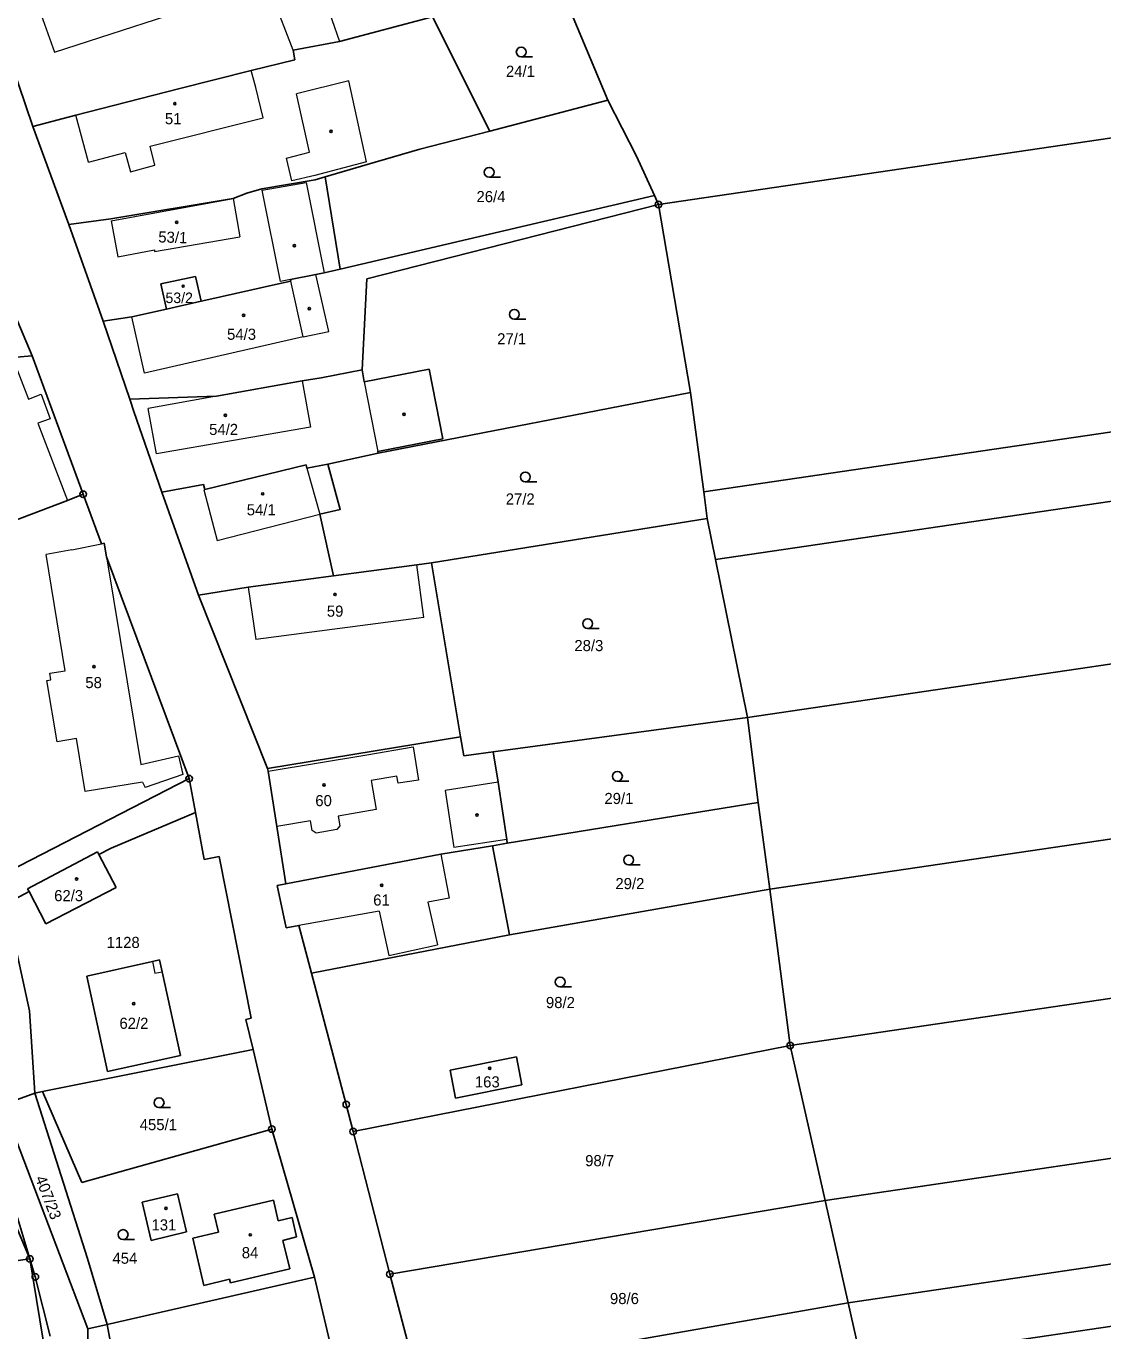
# Model space of a CAD drawing. Extents: x -618848 to -615803, y -1044450 to -1042254.
# Drawn here: x -616929.8 to -616765.3, y -1043345.1 to -1043145.8 of the extents above; entities that cross this region are included whole.
import ezdxf
from ezdxf.enums import TextEntityAlignment as Align

# ---------------------------------------------------------------- set-up
doc = ezdxf.new("R2010")
doc.units = 0
doc.header["$LTSCALE"] = 0.68
for name, color, linetype, lineweight in [('1', 7, 'Continuous', 25), ('3', 7, 'Continuous', 25), ('4', 7, 'Continuous', 13), ('5', 7, 'Continuous', 25), ('8', 7, 'Continuous', 25)]:
    doc.layers.add(name, color=color, linetype=linetype, lineweight=lineweight)
doc.layers.add('2', color=7, linetype='Continuous')

msp = doc.modelspace()

# ---------------------------------------------------------------- linework, layer by layer
at = {"layer": '1'}
for p, q in [((-616840.92, -1043157.18), (-616848.28, -1043139.55)), ((-616928.73, -1043161.2), (-616934.26, -1043144.93)), ((-616881.88, -1043148.18), (-616867.68, -1043144.42)), ((-616867.68, -1043144.42), (-616858.92, -1043161.88)), ((-616648.67, -1043145.97), (-616833.15, -1043173.1)), ((-616881.88, -1043148.18), (-616888.98, -1043149.52)), ((-616888.72, -1043151.02), (-616888.98, -1043149.52)), ((-616895.37, -1043152.64), (-616888.72, -1043151.02)), ((-616895.37, -1043152.64), (-616906.46, -1043155.41)), ((-616906.46, -1043155.41), (-616922.14, -1043159.46)), ((-616858.92, -1043161.88), (-616840.92, -1043157.18)), ((-616836.53, -1043165.69), (-616840.92, -1043157.18)), ((-616928.73, -1043161.2), (-616922.14, -1043159.46)), ((-616928.73, -1043161.2), (-616923.21, -1043176.13)), ((-616869.61, -1043164.66), (-616858.92, -1043161.88)), ((-616877.64, -1043167), (-616869.61, -1043164.66)), ((-616884.06, -1043168.87), (-616877.64, -1043167)), ((-616833.77, -1043171.73), (-616836.53, -1043165.69)), ((-616893.73, -1043170.72), (-616885.62, -1043169.32)), ((-616885.62, -1043169.32), (-616884.06, -1043168.87)), ((-616884.06, -1043168.87), (-616881.78, -1043182.98)), ((-616898.12, -1043172.18), (-616896.02, -1043171.37)), ((-616896.02, -1043171.37), (-616893.73, -1043170.72)), ((-616916.81, -1043175.29), (-616898.12, -1043172.18)), ((-616833.77, -1043171.73), (-616881.78, -1043182.98)), ((-616833.15, -1043173.1), (-616877.7, -1043184.44)), ((-616833.77, -1043171.73), (-616833.15, -1043173.1)), ((-616833.15, -1043173.1), (-616828.26, -1043201.79)), ((-616923.21, -1043176.13), (-616916.81, -1043175.29)), ((-616923.21, -1043176.13), (-616917.99, -1043190.91)), ((-616881.78, -1043182.98), (-616884.23, -1043183.55)), ((-616909.16, -1043185.21), (-616903.87, -1043184.1)), ((-616908.29, -1043189.06), (-616909.16, -1043185.21)), ((-616903.87, -1043184.1), (-616903, -1043187.86)), ((-616890.77, -1043185.12), (-616902.3, -1043187.72)), ((-616889.31, -1043184.79), (-616890.77, -1043185.12)), ((-616885.48, -1043183.8), (-616889.36, -1043184.57)), ((-616889.36, -1043184.57), (-616889.31, -1043184.79)), ((-616884.23, -1043183.55), (-616885.48, -1043183.8)), ((-616878.44, -1043198.36), (-616877.7, -1043184.44)), ((-616928.83, -1043196.23), (-616931.97, -1043188.74)), ((-616908.29, -1043189.06), (-616913.6, -1043190.27)), ((-616903, -1043187.86), (-616908.29, -1043189.06)), ((-616902.3, -1043187.72), (-616903, -1043187.86)), ((-616826.24, -1043216.98), (-616635.31, -1043188.92)), ((-616913.6, -1043190.27), (-616917.99, -1043190.91)), ((-616913.9, -1043202.82), (-616917.99, -1043190.91)), ((-616928.83, -1043196.23), (-616941.77, -1043197.23)), ((-616921.05, -1043217.36), (-616928.83, -1043196.23)), ((-616878.44, -1043198.36), (-616884.71, -1043199.56)), ((-616878.44, -1043198.36), (-616878.1, -1043200.2)), ((-616868.19, -1043198.27), (-616878.1, -1043200.2)), ((-616868.19, -1043198.27), (-616866.12, -1043208.87)), ((-616632.17, -1043199.04), (-616824.43, -1043227.31)), ((-616887.57, -1043200.01), (-616900.67, -1043202.37)), ((-616884.71, -1043199.56), (-616887.57, -1043200.01)), ((-616913.9, -1043202.82), (-616900.67, -1043202.37)), ((-616913.28, -1043204.69), (-616913.9, -1043202.82)), ((-616828.26, -1043201.79), (-616875.97, -1043211.1)), ((-616826.24, -1043216.98), (-616828.26, -1043201.79)), ((-616909.01, -1043217.03), (-616913.28, -1043204.69)), ((-616876.03, -1043210.8), (-616866.12, -1043208.87)), ((-616875.97, -1043211.1), (-616883.67, -1043212.75)), ((-616876.03, -1043210.8), (-616875.97, -1043211.1)), ((-616883.67, -1043212.75), (-616886.9, -1043213.35)), ((-616921.05, -1043217.36), (-616923.46, -1043218.28)), ((-616921.05, -1043217.36), (-616918.23, -1043224.92)), ((-616902.65, -1043215.87), (-616909.01, -1043217.03)), ((-616909.01, -1043217.03), (-616903.43, -1043232.75)), ((-616902.47, -1043216.65), (-616902.65, -1043215.87)), ((-616825.7, -1043221.05), (-616826.24, -1043216.98)), ((-616923.46, -1043218.28), (-616931.9, -1043221.52)), ((-616884.91, -1043220.4), (-616882.79, -1043229.82)), ((-616825.7, -1043221.05), (-616867.84, -1043227.85)), ((-616824.43, -1043227.31), (-616825.7, -1043221.05)), ((-616819.54, -1043251.45), (-616624.78, -1043222.81)), ((-616918.23, -1043224.92), (-616917.83, -1043224.84)), ((-616917.83, -1043224.84), (-616917.49, -1043226.91)), ((-616917.49, -1043226.91), (-616904.84, -1043260.79)), ((-616819.54, -1043251.45), (-616824.43, -1043227.31)), ((-616870.05, -1043228.14), (-616882.79, -1043229.82)), ((-616867.84, -1043227.85), (-616870.05, -1043228.14)), ((-616867.84, -1043227.85), (-616863.41, -1043254.38)), ((-616895.83, -1043231.54), (-616882.79, -1043229.82)), ((-616895.83, -1043231.54), (-616903.43, -1043232.75)), ((-616903.43, -1043232.75), (-616892.86, -1043259.25)), ((-616858.39, -1043256.69), (-616819.54, -1043251.45)), ((-616817.96, -1043264.42), (-616819.54, -1043251.45)), ((-616892.86, -1043259.25), (-616863.41, -1043254.38)), ((-616863.41, -1043254.38), (-616862.92, -1043257.31)), ((-616862.92, -1043257.31), (-616858.39, -1043256.69)), ((-616857.67, -1043261.35), (-616858.39, -1043256.69)), ((-616904.84, -1043260.79), (-616936.5, -1043277.03)), ((-616903.88, -1043265.96), (-616904.84, -1043260.79)), ((-616892.8, -1043259.65), (-616892.86, -1043259.25)), ((-616891.46, -1043268.1), (-616892.8, -1043259.65)), ((-616856.34, -1043270.1), (-616857.67, -1043261.35)), ((-616716.5, -1043263), (-616816.16, -1043277.65)), ((-616856.26, -1043270.66), (-616817.96, -1043264.42)), ((-616816.16, -1043277.65), (-616817.96, -1043264.42)), ((-616916.77, -1043271.39), (-616903.88, -1043265.96)), ((-616902.54, -1043273.15), (-616903.88, -1043265.96)), ((-616890.08, -1043276.83), (-616891.46, -1043268.1)), ((-616866.41, -1043272.32), (-616858.51, -1043271.03)), ((-616858.51, -1043271.03), (-616856.26, -1043270.66)), ((-616858.51, -1043271.03), (-616855.92, -1043284.65)), ((-616856.26, -1043270.66), (-616856.34, -1043270.1)), ((-616918.84, -1043271.99), (-616929.53, -1043277.61)), ((-616918.64, -1043272.38), (-616918.84, -1043271.99)), ((-616918.64, -1043272.38), (-616916.77, -1043271.39)), ((-616916.02, -1043277.39), (-616918.64, -1043272.38)), ((-616902.54, -1043273.15), (-616900.25, -1043272.66)), ((-616895.4, -1043297.39), (-616900.25, -1043272.66)), ((-616866.41, -1043272.32), (-616890.08, -1043276.83)), ((-616890.08, -1043276.83), (-616891.42, -1043277.09)), ((-616890.01, -1043283.59), (-616891.42, -1043277.09)), ((-616938.76, -1043283.04), (-616929.31, -1043278.03)), ((-616929.53, -1043277.61), (-616929.31, -1043278.03)), ((-616929.31, -1043278.03), (-616926.73, -1043282.98)), ((-616916.02, -1043277.39), (-616926.73, -1043282.98)), ((-616855.92, -1043284.65), (-616816.16, -1043277.65)), ((-616813.03, -1043301.56), (-616816.16, -1043277.65)), ((-616931.81, -1043284.55), (-616929.24, -1043296.24)), ((-616888.1, -1043283.24), (-616890.01, -1043283.59)), ((-616886.17, -1043290.52), (-616888.1, -1043283.24)), ((-616886.17, -1043290.52), (-616855.92, -1043284.65)), ((-616813.03, -1043301.56), (-616711.32, -1043286.6)), ((-616910.46, -1043288.72), (-616920.49, -1043290.94)), ((-616909.38, -1043288.47), (-616910.46, -1043288.72)), ((-616908.98, -1043290.29), (-616909.38, -1043288.47)), ((-616920.49, -1043290.94), (-616917.31, -1043305.52)), ((-616906.19, -1043303.06), (-616908.98, -1043290.29)), ((-616880.85, -1043310.56), (-616886.17, -1043290.52)), ((-616929.24, -1043296.24), (-616928.44, -1043308.83)), ((-616896.18, -1043297.56), (-616895.4, -1043297.39)), ((-616896.18, -1043297.56), (-616895.09, -1043302.15)), ((-616927.24, -1043308.59), (-616895.09, -1043302.15)), ((-616917.31, -1043305.52), (-616906.19, -1043303.06)), ((-616895.09, -1043302.15), (-616892.21, -1043314.31)), ((-616813.03, -1043301.56), (-616879.8, -1043314.69)), ((-616807.71, -1043325.2), (-616813.03, -1043301.56)), ((-616865, -1043305.3), (-616854.84, -1043303.28)), ((-616854.84, -1043303.28), (-616854.01, -1043307.56)), ((-616864.18, -1043309.58), (-616865, -1043305.3)), ((-616933.31, -1043310.62), (-616928.44, -1043308.83)), ((-616928.44, -1043308.83), (-616927.24, -1043308.59)), ((-616928.44, -1043308.83), (-616920.38, -1043334.09)), ((-616927.24, -1043308.59), (-616921.26, -1043322.47)), ((-616854.01, -1043307.56), (-616864.18, -1043309.58)), ((-616929.18, -1043334.15), (-616939.28, -1043310.49)), ((-616933.31, -1043310.62), (-616920.31, -1043344.84)), ((-616879.8, -1043314.69), (-616880.85, -1043310.56)), ((-616705.02, -1043310.1), (-616807.71, -1043325.2)), ((-616929.18, -1043334.15), (-616935.98, -1043311.61)), ((-616921.26, -1043322.47), (-616892.21, -1043314.31)), ((-616885.69, -1043336.95), (-616892.21, -1043314.31)), ((-616874.19, -1043336.49), (-616879.8, -1043314.69)), ((-616912.03, -1043325.49), (-616906.64, -1043324.19)), ((-616906.64, -1043324.19), (-616905.24, -1043330.03)), ((-616910.63, -1043331.32), (-616912.03, -1043325.49)), ((-616891.99, -1043325.17), (-616901.02, -1043327.29)), ((-616891.24, -1043328.31), (-616891.99, -1043325.17)), ((-616807.71, -1043325.2), (-616874.19, -1043336.49)), ((-616804.19, -1043340.84), (-616807.71, -1043325.2)), ((-616804.19, -1043340.84), (-616700.86, -1043325.65)), ((-616901.02, -1043327.29), (-616900.36, -1043330.08)), ((-616889.13, -1043327.8), (-616891.24, -1043328.31)), ((-616888.43, -1043330.78), (-616889.13, -1043327.8)), ((-616905.24, -1043330.03), (-616910.63, -1043331.32)), ((-616904.3, -1043331), (-616900.36, -1043330.08)), ((-616888.43, -1043330.78), (-616890.52, -1043331.31)), ((-616904.3, -1043331), (-616902.61, -1043338.18)), ((-616889.48, -1043335.66), (-616890.52, -1043331.31)), ((-616998.06, -1043343.8), (-616929.18, -1043334.15)), ((-616925.06, -1043359.49), (-616929.18, -1043334.15)), ((-616928.35, -1043336.89), (-616929.18, -1043334.15)), ((-616920.38, -1043334.09), (-616917.4, -1043344.15)), ((-616698.42, -1043334.78), (-616802.12, -1043350.03)), ((-616926.08, -1043345.94), (-616928.35, -1043336.89)), ((-616917.4, -1043344.15), (-616885.69, -1043336.95)), ((-616898.56, -1043337.82), (-616889.48, -1043335.66)), ((-616885.69, -1043336.95), (-616881.84, -1043353.24)), ((-616874.19, -1043336.49), (-616870.05, -1043352.35)), ((-616902.61, -1043338.18), (-616898.7, -1043337.23)), ((-616898.7, -1043337.23), (-616898.56, -1043337.82)), ((-616870.05, -1043352.35), (-616804.19, -1043340.84)), ((-616802.12, -1043350.03), (-616804.19, -1043340.84)), ((-616920.31, -1043344.84), (-616920.36, -1043359.35)), ((-616917.4, -1043344.15), (-616920.31, -1043344.84)), ((-616917.4, -1043344.15), (-616916.06, -1043351.13))]:
    msp.add_line(p, q, dxfattribs=at)
for points in [[(-616886.9, -1043213.35), (-616886.99, -1043212.86), (-616902.47, -1043216.65)], [(-616883.67, -1043212.75), (-616881.77, -1043219.67), (-616884.91, -1043220.4)]]:
    msp.add_lwpolyline(points, dxfattribs=at)
at = {"layer": '3'}
for p, q in [((-616854.133, -1043150.56), (-616852.383, -1043150.56)), ((-616859.023, -1043168.92), (-616857.273, -1043168.92)), ((-616855.183, -1043190.63), (-616853.433, -1043190.63)), ((-616853.503, -1043215.46), (-616851.753, -1043215.46)), ((-616843.973, -1043237.86), (-616842.223, -1043237.86)), ((-616839.433, -1043261.18), (-616837.683, -1043261.18)), ((-616837.723, -1043273.97), (-616835.973, -1043273.97)), ((-616848.183, -1043292.6), (-616846.433, -1043292.6)), ((-616909.443, -1043311.03), (-616907.693, -1043311.03)), ((-616914.943, -1043331.17), (-616913.193, -1043331.17))]:
    msp.add_line(p, q, dxfattribs=at)
for centre in [(-616854.1329, -1043149.8098), (-616859.0229, -1043168.1698), (-616855.1829, -1043189.8798), (-616853.5029, -1043214.7098), (-616843.9729, -1043237.1098), (-616839.4329, -1043260.4298), (-616837.7229, -1043273.2198), (-616848.1829, -1043291.8498), (-616909.4429, -1043310.2798), (-616914.9429, -1043330.4198)]:
    msp.add_circle(centre, 0.75, dxfattribs=at)
at = {"layer": '4'}
for p, q in [((-616885.68, -1043137.19), (-616881.88, -1043148.18)), ((-616925.41, -1043149.83), (-616892.89, -1043139.27)), ((-616888.98, -1043149.52), (-616892.89, -1043139.27)), ((-616927.98, -1043142.68), (-616925.41, -1043149.83)), ((-616894.69, -1043155.24), (-616895.37, -1043152.64)), ((-616893.55, -1043159.87), (-616894.69, -1043155.24)), ((-616880.48, -1043154.22), (-616888.44, -1043156.2)), ((-616877.77, -1043166.56), (-616880.48, -1043154.22)), ((-616886.49, -1043165.12), (-616888.44, -1043156.2)), ((-616920.22, -1043166.64), (-616922.14, -1043159.46)), ((-616910.82, -1043164.2), (-616893.55, -1043159.87)), ((-616920.22, -1043166.64), (-616914.62, -1043165.17)), ((-616914.62, -1043165.17), (-616913.83, -1043168.08)), ((-616910.12, -1043167.1), (-616910.82, -1043164.2)), ((-616889.98, -1043166.02), (-616886.49, -1043165.12)), ((-616913.83, -1043168.08), (-616910.12, -1043167.1)), ((-616889.16, -1043169.49), (-616889.98, -1043166.02)), ((-616877.77, -1043166.56), (-616885.65, -1043168.65)), ((-616885.65, -1043168.65), (-616889.16, -1043169.49)), ((-616893.69, -1043170.91), (-616887, -1043169.72)), ((-616890.88, -1043184.87), (-616893.69, -1043170.91)), ((-616887, -1043169.72), (-616884.23, -1043183.55)), ((-616916.76, -1043175.58), (-616915.77, -1043181.1)), ((-616910.13, -1043180.28), (-616897.09, -1043178.02)), ((-616915.77, -1043181.1), (-616910.17, -1043180.04)), ((-616910.17, -1043180.04), (-616910.13, -1043180.28)), ((-616889.36, -1043184.57), (-616890.88, -1043184.87)), ((-616887.44, -1043193.33), (-616889.31, -1043184.79)), ((-616883.53, -1043192.5), (-616885.48, -1043183.8)), ((-616911.65, -1043198.85), (-616913.6, -1043190.27)), ((-616887.44, -1043193.33), (-616911.65, -1043198.85)), ((-616887.44, -1043193.33), (-616883.53, -1043192.5)), ((-616931.36, -1043197.66), (-616929.38, -1043202.83)), ((-616887.57, -1043200.01), (-616886.3, -1043207.1)), ((-616878.1, -1043200.2), (-616876.03, -1043210.8)), ((-616929.38, -1043202.83), (-616927.44, -1043202.07)), ((-616927.44, -1043202.07), (-616926.1, -1043205.81)), ((-616900.67, -1043202.37), (-616911.1, -1043204.24)), ((-616909.85, -1043211.2), (-616911.1, -1043204.24)), ((-616926.1, -1043205.81), (-616927.98, -1043206.48)), ((-616927.98, -1043206.48), (-616923.46, -1043218.28)), ((-616886.3, -1043207.1), (-616909.85, -1043211.2)), ((-616886.9, -1043213.35), (-616884.91, -1043220.4)), ((-616902.47, -1043216.65), (-616902.62, -1043216.69)), ((-616902.62, -1043216.69), (-616900.57, -1043224.41)), ((-616900.57, -1043224.41), (-616884.91, -1043220.4)), ((-616922.75, -1043225.83), (-616918.23, -1043224.92)), ((-616922.75, -1043225.83), (-616926.71, -1043226.55)), ((-616923.77, -1043244.31), (-616926.71, -1043226.55)), ((-616917.49, -1043226.91), (-616912.24, -1043258.62)), ((-616868.99, -1043236.16), (-616870.05, -1043228.14)), ((-616895.83, -1043231.54), (-616894.67, -1043239.55)), ((-616868.99, -1043236.16), (-616894.67, -1043239.55)), ((-616926.14, -1043244.7), (-616923.77, -1043244.31)), ((-616892.8, -1043259.65), (-616877.69, -1043257.15)), ((-616877.69, -1043257.15), (-616870.62, -1043255.93)), ((-616870.62, -1043255.93), (-616869.84, -1043261.01)), ((-616912.24, -1043258.62), (-616906.5, -1043257.32)), ((-616906.5, -1043257.32), (-616905.83, -1043260.17)), ((-616905.83, -1043260.17), (-616911.56, -1043262.14)), ((-616873.12, -1043260.42), (-616877.03, -1043261.05)), ((-616877.03, -1043261.05), (-616876.27, -1043265.51)), ((-616872.95, -1043261.48), (-616873.12, -1043260.42)), ((-616869.84, -1043261.01), (-616872.95, -1043261.48)), ((-616912, -1043261.31), (-616920.72, -1043262.76)), ((-616912, -1043261.31), (-616911.56, -1043262.14)), ((-616857.67, -1043261.35), (-616865.75, -1043262.59)), ((-616865.75, -1043262.59), (-616864.42, -1043271.33)), ((-616876.27, -1043265.51), (-616882.09, -1043266.5)), ((-616882.09, -1043266.5), (-616881.83, -1043268)), ((-616886.32, -1043267.22), (-616891.46, -1043268.1)), ((-616886.04, -1043268.7), (-616886.32, -1043267.22)), ((-616885.45, -1043269.12), (-616886.04, -1043268.7)), ((-616882.27, -1043268.58), (-616885.45, -1043269.12)), ((-616881.83, -1043268), (-616882.27, -1043268.58)), ((-616856.34, -1043270.1), (-616864.42, -1043271.33)), ((-616866.41, -1043272.32), (-616865.12, -1043279.06)), ((-616865.12, -1043279.06), (-616868.37, -1043279.65)), ((-616875.82, -1043281.01), (-616888.1, -1043283.24)), ((-616875.82, -1043281.01), (-616874.34, -1043287.8)), ((-616868.37, -1043279.65), (-616866.94, -1043286.19)), ((-616874.34, -1043287.8), (-616866.94, -1043286.19)), ((-616910.46, -1043288.72), (-616910.08, -1043290.52)), ((-616910.08, -1043290.52), (-616908.98, -1043290.29))]:
    msp.add_line(p, q, dxfattribs=at)
for points in [[(-616916.76, -1043175.58), (-616898.12, -1043172.18), (-616897.09, -1043178.02)], [(-616920.72, -1043262.76), (-616922.06, -1043254.67), (-616925.02, -1043255.16), (-616926.57, -1043245.78), (-616925.98, -1043245.69), (-616926.14, -1043244.7)]]:
    msp.add_lwpolyline(points, dxfattribs=at)
at = {"layer": '5'}
for centre in [(-616907.0368, -1043157.6892), (-616883.1668, -1043161.9392), (-616906.7568, -1043175.8189), (-616888.7768, -1043179.3892), (-616905.7668, -1043185.5689), (-616886.5068, -1043188.9892), (-616896.5368, -1043190.0092), (-616899.3168, -1043205.2892), (-616872.0268, -1043205.1392), (-616893.6168, -1043217.2892), (-616882.5668, -1043232.6592), (-616919.4068, -1043243.6692), (-616884.2468, -1043261.7492), (-616860.8868, -1043266.3592), (-616922.0468, -1043276.1192), (-616875.4368, -1043277.0792), (-616913.3068, -1043295.1692), (-616858.9368, -1043305.0292), (-616908.3868, -1043326.4392), (-616895.5168, -1043330.4692)]:
    msp.add_circle(centre, 0.175, dxfattribs=at)
at = {"layer": '8'}
for centre, radius in [((-616833.15, -1043173.0999), 0.5), ((-616833.15, -1043173.0999), 0.0303), ((-616921.05, -1043217.3599), 0.5), ((-616921.05, -1043217.3599), 0.0303), ((-616904.84, -1043260.7899), 0.5), ((-616904.84, -1043260.7899), 0.0303), ((-616813.03, -1043301.5599), 0.5), ((-616813.03, -1043301.5599), 0.0303), ((-616880.85, -1043310.5599), 0.5), ((-616880.85, -1043310.5599), 0.0303), ((-616892.21, -1043314.3099), 0.5), ((-616892.21, -1043314.3099), 0.0303), ((-616879.8, -1043314.6899), 0.5), ((-616879.8, -1043314.6899), 0.0303), ((-616929.18, -1043334.1499), 0.5), ((-616929.18, -1043334.1499), 0.0303), ((-616928.35, -1043336.8899), 0.5), ((-616928.35, -1043336.8899), 0.0303), ((-616874.19, -1043336.4899), 0.5), ((-616874.19, -1043336.4899), 0.0303)]:
    msp.add_circle(centre, radius, dxfattribs=at)

# ---------------------------------------------------------------- texts
at = {"layer": '2'}
for s, p in [('24/1', (-616854.249, -1043153.595)), ('51', (-616907.289, -1043160.835)), ('26/4', (-616858.749, -1043172.735)), ('54/3', (-616896.849, -1043193.765)), ('27/1', (-616855.589, -1043194.455)), ('54/2', (-616899.589, -1043208.295)), ('27/2', (-616854.279, -1043218.925)), ('54/1', (-616893.839, -1043220.575)), ('59', (-616882.559, -1043236.055)), ('28/3', (-616843.799, -1043241.315)), ('58', (-616919.449, -1043246.965)), ('29/1', (-616839.209, -1043264.665)), ('60', (-616884.319, -1043264.995)), ('29/2', (-616837.529, -1043277.665)), ('62/3', (-616923.259, -1043279.505)), ('61', (-616875.469, -1043280.175)), ('1128', (-616914.93, -1043286.655)), ('98/2', (-616848.139, -1043295.835)), ('62/2', (-616913.289, -1043299.005)), ('163', (-616859.309, -1043307.955)), ('455/1', (-616909.56, -1043314.485)), ('98/7', (-616842.149, -1043319.985)), ('131', (-616908.709, -1043329.795)), ('84', (-616895.549, -1043334.045)), ('454', (-616914.669, -1043334.885)), ('98/6', (-616838.359, -1043341.045))]:
    msp.add_text(s, height=1.7, dxfattribs=at).set_placement(p, align=Align.CENTER)
for s, rotation, p in [('53/1', 358, (-616907.3797, -1043178.9545)), ('407/23', 291, (-616927.1574, -1043325.0569))]:
    msp.add_text(s, height=1.7, rotation=rotation, dxfattribs=at).set_placement(p, align=Align.CENTER)
msp.add_text('53/2', height=1.612, dxfattribs=at).set_placement((-616908.47, -1043188.153))

doc.saveas('drawing.dxf')
